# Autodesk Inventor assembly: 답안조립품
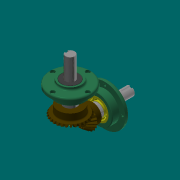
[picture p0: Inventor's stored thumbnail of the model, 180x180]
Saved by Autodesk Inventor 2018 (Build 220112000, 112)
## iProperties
Created: 2023-01
Part Number: 답안조립품
Material: 일반
Document SubType Name: Assembly
Designer: 강의실01
Author: 강의실01
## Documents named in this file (13)
- C:\Users\kimgi\Desktop\730106V1009\답안조립품.iam
- C:\Users\kimgi\Desktop\730106V1009\본체.ipt
- C:\Users\kimgi\Desktop\730106V1009\커버.ipt
- C:\Users\kimgi\Desktop\730106V1009\베어링 6203.ipt
- C:\Users\kimgi\Desktop\730106V1009\메인 축.ipt
- 메인 축.ipt
- C:\Users\kimgi\Desktop\730106V1009\오일실 17 32 8.ipt
- C:\Users\kimgi\Desktop\730106V1009\키 5x5.ipt
- C:\Users\kimgi\Desktop\730106V1009\메인 베벨기어.ipt
- C:\Users\kimgi\Desktop\730106V1009\서브 축.ipt
- 서브 축.ipt
- C:\Users\kimgi\Desktop\730106V1009\키 4x4.ipt
- C:\Users\kimgi\Desktop\730106V1009\서브 베벨기어.ipt
